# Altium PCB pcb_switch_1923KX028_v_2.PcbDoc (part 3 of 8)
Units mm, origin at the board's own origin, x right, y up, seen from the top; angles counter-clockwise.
Board outline 297.2 x 112.05 mm, 6 copper layers (Component Side, GND Layer 1, Inner Layer 1, Inner Layer 2, GND Layer 2, Solder Side), stack 1.578 mm thick; 545 components, 377 nets, 3174 pads, 1537 vias.
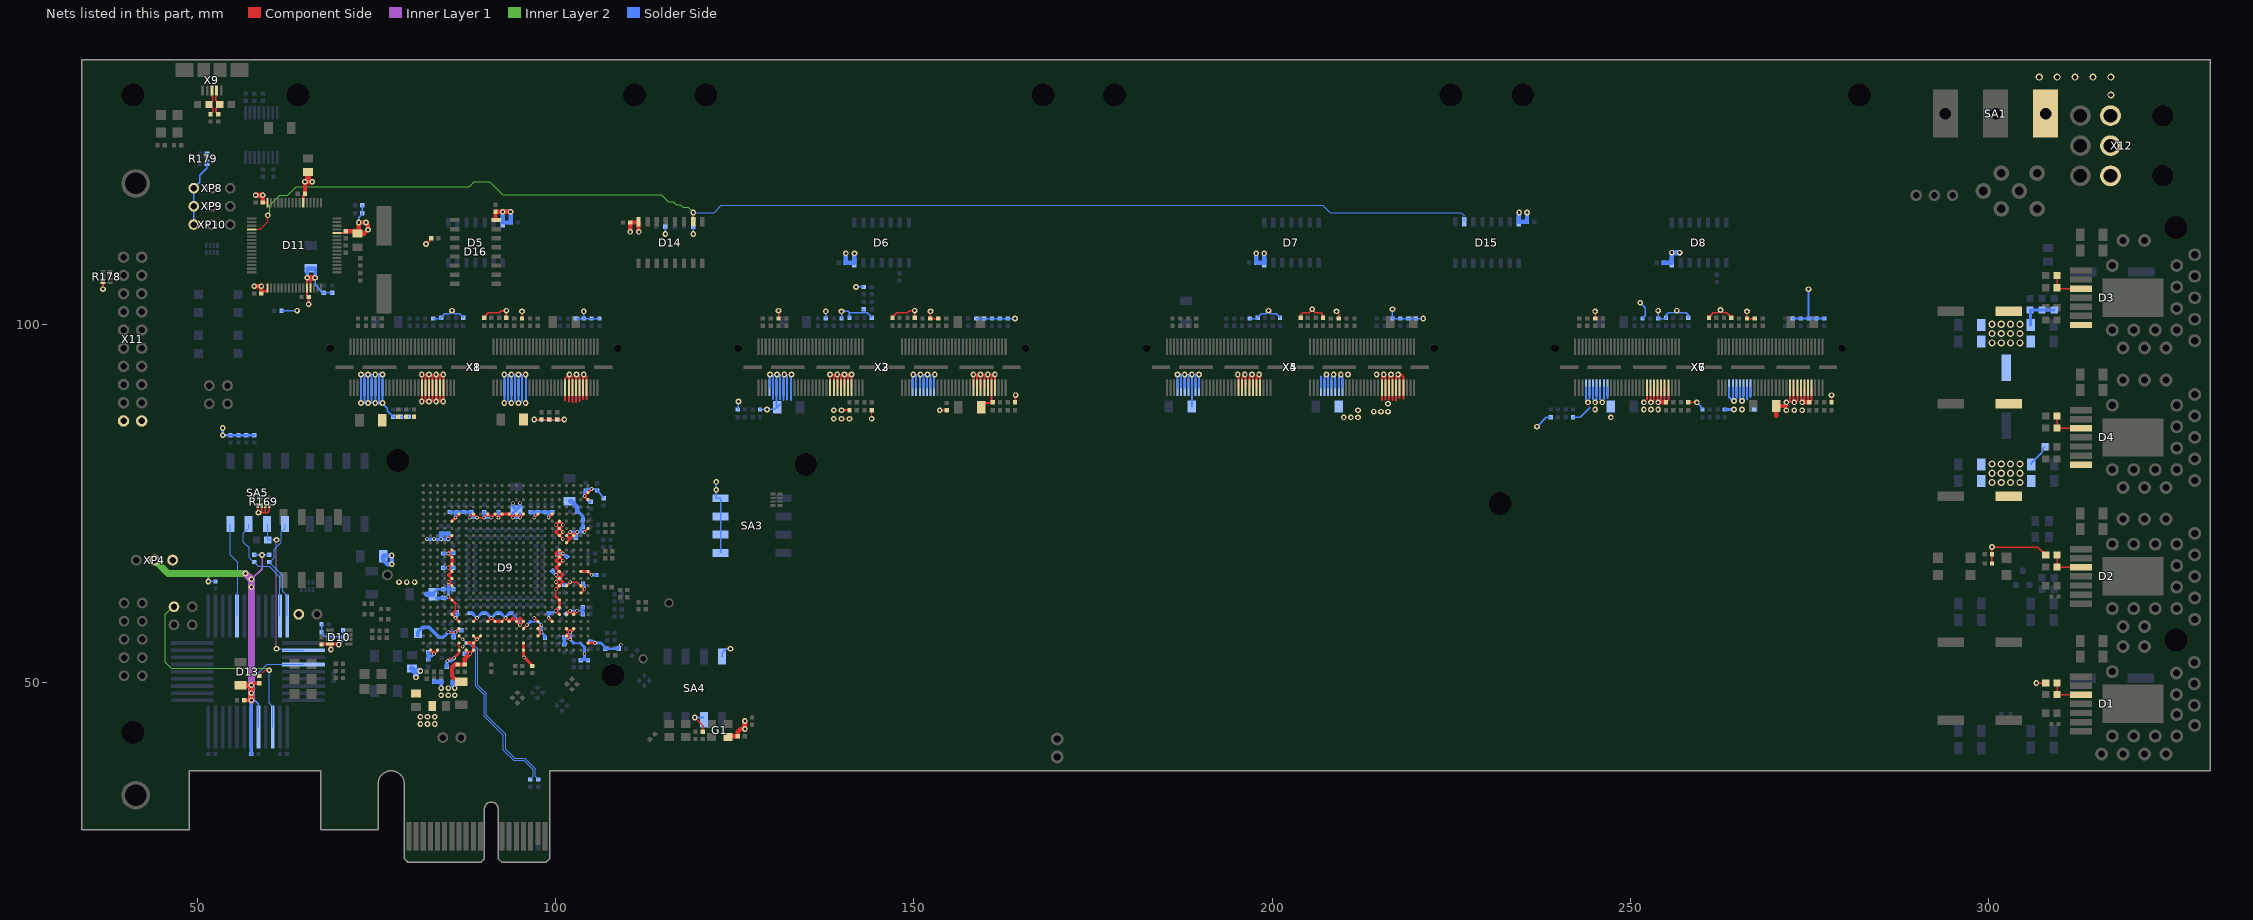
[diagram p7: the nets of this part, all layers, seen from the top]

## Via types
v1: diameter 0.8, hole 0.4, Component Side to Solder Side, tented both sides, 884 vias
v2: diameter 0.5, hole 0.3, Component Side to Solder Side, tented both sides, 269 vias
v3: diameter 1, hole 0.6, Component Side to Solder Side, tented both sides, 95 vias
v4: diameter 0.5/0.5/0.3/0.3/0.5/0.5 (per signal layer), hole 0.3, Component Side to Solder Side, tented both sides, 80 vias
v5: diameter 0.5/0.3/0.3/0.5/0.3/0.5 (per signal layer), hole 0.3, Component Side to Solder Side, tented both sides, 37 vias
v6: diameter 0.5/0.3/0.3/0.3/0.3/0.5 (per signal layer), hole 0.3, Component Side to Solder Side, tented both sides, 34 vias
v7: diameter 0.5/0.5/0.5/0.3/0.5/0.5 (per signal layer), hole 0.3, Component Side to Solder Side, tented both sides, 29 vias
v8: diameter 0.5, hole 0.3, Component Side to Solder Side, 25 vias
v9: diameter 0.5/0.3/0.5/0.3/0.3/0.5 (per signal layer), hole 0.3, Component Side to Solder Side, tented both sides, 25 vias
v10: diameter 0.5/0.5/0.3/0.5/0.5/0.5 (per signal layer), hole 0.3, Component Side to Solder Side, tented both sides, 19 vias
v11: diameter 0.6, hole 0.3, Component Side to Solder Side, tented both sides, 14 vias
v12: diameter 0.8, hole 0.5, Component Side to Solder Side, tented both sides, 11 vias
v13: diameter 0.5/0.3/0.5/0.5/0.3/0.5 (per signal layer), hole 0.3, Component Side to Solder Side, tented both sides, 7 vias
v14: diameter 0.8, hole 0.4, Component Side to Solder Side, 5 vias
v15: diameter 0.5/0.5/0.5/0.5/0.5/0.5 (per signal layer), hole 0.3, Component Side to Solder Side, tented both sides, 2 vias
v16: diameter 0.8, hole 0.5, Component Side to Solder Side, 1 vias

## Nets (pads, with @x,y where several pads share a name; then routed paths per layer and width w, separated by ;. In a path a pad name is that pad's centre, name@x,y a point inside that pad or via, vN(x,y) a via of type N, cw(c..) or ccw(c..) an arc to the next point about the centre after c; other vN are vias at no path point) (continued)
+3.3V: C4.1 C5.1 C11.1 C12.1 C13.1 C15.1 C16.1 C17.1 C18.2 C19.1 C21.1 C23.1 C25.1 C27.1 C29.1 C31.2 C32.2 C33.2 C34.2 C35.1 C40.1 C56.1 C65.1 C66.1 C74.1 C75.1 C83.1 C85.1 C96.2 C108.1 C119.2 C121.2 C122.2 C123.2 C124.2 C125.1 C126.2 C139.1 C155.1 C159.1 C160.1 C161.1 C162.1 C163.1 C164.1 C165.1 C166.1 C167.1 C168.1 C169.1 C170.1 C172.1 C174.1 C175.1 C176.1 C177.1 C178.1 C179.1 C180.1 C181.1 C182.1 C183.1 C184.1 C187.1 C190.1 C223.1 C228.1 C229.1 C230.1 C231.1 C232.1 C233.1 C234.1 C235.1 C236.1 C237.1 C238.1 D3.7 D4.7 D5.14 D6.14 D7.14 D8.14 D9.AC24 D9.AD2 D9.AD3 D9.B24 D9.C24 D9.E6 D9.E8 D9.E10 D9.E11 D9.E12 D9.E13 D9.E14 D9.E15 D9.E17 D9.E19 D9.F5 D9.F20 D9.G20 D9.H5 D9.H20 D9.K5 D9.K20 D9.L5 D9.L20 D9.M5 D9.M20 D9.N5 D9.N20 D9.P5 D9.P20 D9.R5 D9.R20 D9.U5 D9.U20 D9.V20 D9.W5 D9.W20 D9.Y6 D9.Y8 D9.Y10 D9.Y11 D9.Y12 D9.Y13 D9.Y14 D9.Y15 D9.Y17 D9.Y19 D10.8 D11.1 D11.12 D11.13 D11.28 D11.38 D11.48 D14.16 D15.16 D16.16 G1.4 L1.1 L4.1 L5.1 L6.2 R4.2 R5.2 R6.1 R13.1 R14.1 R15.1 R16.1 R17.1 R18.1 R19.1 R20.1 R25.1 R26.1 R27.1 R28.1 R29.1 R31.2 R32.1 R33.1 R36.1 R43.1 R51.1 R53.2 R57.2 R59.1 R60.1 R61.1 R66.1 R67.1 R68.1 R69.1 R72.1 R73.1 R74.1 R75.1 R76.1 R77.1 R84.1 R85.1 R88.1 R89.1 R90.1 R91.1 R92.1 R93.1 R98.1 R99.1 R100.1 R101.1 R103.1 R104.1 R109.2 R110.2 R112.1 R113.1 R116.2 R117.2 R122.2 R124.2 R126.2 R131.2 R147.2 R150.2 R152.1 R154.2 R156.2 R158.2 R161.2 R164.2 R165.2 R167.2 R169.1 R169.2 R169.3 R169.4 R171.1 R173.1 R175.1 R176.2 R177.2 R178.4 R179.5 R179.6 R179.7 R179.8 R181.1 R182.1 R183.1 R184.1 R185.1 R186.2 R189.2 R196.2 R199.2 R204.2 R206.2 R208.2 R209.2 R210.2 R211.2 R212.2 R213.2 R217.2 R218.2 R219.2 R228.1 R229.1 R230.1 R231.1 R232.1 R233.1 R234.1 SA3.1 SA3.2 SA3.3 SA3.4 SA4.4 X1.41 X1.43 X1.45 X1.47 X1.49 X1.51 X1.53 X1.101 X1.103 X1.105 X1.107 X1.109 X1.111 X1.113 X2.41 X2.43 X2.45 X2.47 X2.49 X2.51 X2.53 X2.101 X2.103 X2.105 X2.107 X2.109 X2.111 X2.113 X3.41 X3.43 X3.45 X3.47 X3.49 X3.51 X3.53 X3.101 X3.103 X3.105 X3.107 X3.109 X3.111 X3.113 X4.41 X4.43 X4.45 X4.47 X4.49 X4.51 X4.53 X4.101 X4.103 X4.105 X4.107 X4.109 X4.111 X4.113 X5.41 X5.43 X5.45 X5.47 X5.49 X5.51 X5.53 X5.101 X5.103 X5.105 X5.107 X5.109 X5.111 X5.113 X6.41 X6.43 X6.45 X6.47 X6.49 X6.51 X6.53 X6.101 X6.103 X6.105 X6.107 X6.109 X6.111 X6.113 X7.41 X7.43 X7.45 X7.47 X7.49 X7.51 X7.53 X7.101 X7.103 X7.105 X7.107 X7.109 X7.111 X7.113 X8.41 X8.43 X8.45 X8.47 X8.49 X8.51 X8.53 X8.101 X8.103 X8.105 X8.107 X8.109 X8.111 X8.113 X11.1 X11.2 XP4.3 XP8.1 XP9.1 XP10.1 XP11.1 | length 672.1
  Component Side w0.15: v1(144.1,86.8) R18.1@144.1,88
  Component Side w0.2: R169.1@58.4,74.725 58.4,73.7 v1(58.5,73.7) 58.95,73.7 ; R169.2@58.95,74.725 58.95,73.7 ; R169.3@59.45,74.725 59.45,73.7 ; R169.4@60,74.725 60,74 59.7,73.7 59.45,73.7 ; v1(81.9,111.2) 82.6,111.9 R234.1@82.6,112 ; 86,60 86,61 ; v6(89,73) v6(90,73) ; R27.1@90,100.9 90,101 90.6,101.6 92.1,101.6 92.4,101.9 v1(93.1,101.9) R28.1@93.1,100.9 ; R147.2@95.3,100.8 v1(95.3,101.8) ; v1(97,86.7) R184.1@98,86.7 R185.1@99.1,86.7 R183.1@100.2,86.7 v1(101.2,86.7) ; 100,62 v9(100,63) ; R131.2@131.1,100.8 v1(131.1,101.9) ; R29.1@147,100.9 147,101 147.6,101.6 149.1,101.6 149.4,101.9 v1(150.1,101.9) R32.1@150.1,100.9 ; v1(152.3,101.8) R156.2@152.3,100.8 R158.2@153.4,100.8 ; v1(153.6,88) R100.1@154.6,88 ; R72.1@204,100.9 204,101.3 204.3,101.6 205.2,101.6 205.6,102 206,101.6 206.8,101.6 207.1,101.3 R73.1@207.1,100.9 ; v1(209,101.8) 209.3,101.5 R204.2@209.3,100.8 ; R196.2@245.1,100.8 v1(245.1,101.8) ; R69.1@258.1,89.1 v1(259.3,89.1) ; R76.1@261,100.9 261,101 261.6,101.6 262.2,101.6 v1(262.6,102) 263,101.6 263.5,101.6 264.1,101 R77.1@264.1,100.9 ; v1(266.3,101.8) R206.2@266.3,100.8 R208.2@267.4,100.8 ; R85.1@278.1,89.1 v1(278.1,90.1) ; R31.2@300.5,66.6 R33.1@300.5,67.9 v1(300.5,68.9) 306.9,68.9 R43.1@308,67.8 ; v1(306.7,49.9) R36.1@308,49.9 ; 58.95,73.7 59.45,73.7
  Component Side w0.28: v1@81.315,89.215 X1.41@81.315,91.135 v1@81.315,92.985 ; 81.815,89.215 X1.43@81.815,91.135 81.815,92.985 ; v1@82.315,89.215 X1.45@82.315,91.135 v1@82.315,92.985 ; 82.815,89.215 X1.47@82.815,91.135 82.815,92.985 ; v1@83.315,89.215 X1.49@83.315,91.135 v1@83.315,92.985 ; 83.815,89.215 X1.51@83.815,91.135 83.815,92.985 ; v1@84.315,89.215 X1.53@84.315,91.135 v1@84.315,92.985 ; 101.32,89.38 X1.101@101.32,91.135 101.32,92.42 101.6,92.7 ; 101.82,89.22 X1.103@101.82,91.135 v1@101.82,92.78 ; 102.32,89.12 X1.105@102.32,91.135 102.32,92.72 ; 102.82,89.18 X1.107@102.82,91.135 v1@102.82,92.78 ; 103.32,89.28 X1.109@103.32,91.135 103.32,92.72 ; 103.82,89.58 X1.111@103.82,91.135 v1@103.82,92.78 ; 104.32,89.52 X1.113@104.32,91.135 104.32,92.72 ; X2.41@138.315,91.135 v1@138.315,92.985 ; X2.43@138.815,91.135 138.815,92.985 ; X2.45@139.315,91.135 v1@139.315,92.985 ; X2.47@139.815,91.135 139.815,92.985 ; v1(139.9,88) R17.1@141,88 ; X2.49@140.315,91.135 v1@140.315,92.985 ; X2.51@140.815,91.135 140.815,93.085 ; X2.53@141.315,91.135 v1@141.315,92.985 ; X2.101@158.32,91.135 v1@158.32,92.98 ; X2.103@158.82,91.135 158.82,93.08 ; X2.105@159.32,91.135 v1@159.32,92.98 ; C21.1@159.4,88.4 160,89 160.92,89 R51.1@161.02,89.1 ; X2.107@159.82,91.135 159.82,92.98 ; X2.109@160.32,91.135 v1@160.32,92.98 ; R51.1@160.82,89.1 X2.111@160.82,91.135 160.82,93.08 ; X2.113@161.32,91.135 v1@161.32,92.98 ; R59.1@164.12,89.1 164.2,89.18 v1(164.2,90.1) ; X4.41@195.315,91.135 v1@195.315,92.885 ; X4.43@195.815,91.135 195.815,92.615 ; X4.45@196.315,91.135 v1@196.315,92.885 ; X4.47@196.815,91.135 196.815,92.615 ; X4.49@197.315,91.135 v1@197.315,92.885 ; X4.51@197.815,91.135 197.815,92.785 ; X4.53@198.315,91.135 v1@198.315,92.885 ; 215.32,89.42 X4.101@215.32,91.135 v1@215.32,92.72 ; 215.82,89.48 X4.103@215.82,91.135 v1@215.82,92.78 ; 216.32,89.42 X4.105@216.32,91.135 v1@216.32,92.72 ; 216.82,89.42 X4.107@216.82,91.135 v1@216.82,92.78 ; 217.32,89.38 X4.109@217.32,91.135 v1@217.32,92.72 ; v1(217.6,93) 218,93 218.32,92.68 X4.113@218.32,91.135 218.32,89.62 ; 217.82,89.72 X4.111@217.82,91.135 v1@217.82,92.78 ; 252.315,89.515 X6.41@252.315,91.135 ; 252.815,89.515 X6.43@252.815,91.135 ; 253.315,89.415 X6.45@253.315,91.135 ; v1@253.815,89.185 X6.47@253.815,91.135 ; v1(253.9,89.1) 254.315,89.515 X6.49@254.315,91.135 ; X6.51@254.815,91.135 254.815,89.285 R68.1@255,89.1 255.315,89.415 X6.53@255.315,91.135 ; 272.32,89.12 X6.101@272.32,91.135 ; v1@272.82,89.18 X6.103@272.82,91.135 ; 273.32,89.28 X6.105@273.32,91.135 ; v1@273.82,89.28 X6.107@273.82,91.135 ; 274.32,89.42 X6.109@274.32,91.135 ; R84.1@274.82,89.28 X6.111@274.82,91.135 ; R84.1@275,89.1 275.32,89.42 X6.113@275.32,91.135
  Component Side w0.3: v1(36.8,104.9) R178.4@36.8,105.8 ; C122.2@58.9,104.3 58.9,104.6 59.75,104.6 D11.1@59.75,105.05 ; C124.2@59.1,117 59.7,117 D11.48@59.75,116.95 ; D11.38@64.75,116.95 64.75,117.95 C126.2@65,118.2 ; v1@65.25,106.5 D11.12@65.25,105.05 65.25,104.05 C123.2@65.5,103.8 v1(65.5,102.8) ; D11.13@65.75,105.05 65.75,106.5 ; D11.28@69.45,112.75 70.45,112.75 C119.2@70.7,113
  Component Side w0.4: C96.2@67.3,55.3 67.3,55.35 D10.8@68.5,55.35 D10.8@68.6,55.35 ; v1(68.6,54.6) D10.8@68.6,55.35 ; v1(69.7,55.3) 69.65,55.35 D10.8@68.6,55.35 ; D9.AD2@82.5,54.5 v7(83,54) D9.AD3@83.5,54.5 ; v7(85,62) D9.U5@85.5,61.5 86,61 ; v7(85,70) D9.H5@85.5,70.5 ; D9.R5@85.5,63.5 v7(85,64) D9.P5@85.5,64.5 85,65 D9.N5@85.5,65.5 v7(85,66) D9.M5@85.5,66.5 D9.L5@85.5,67.5 v7(85,68) D9.K5@85.5,68.5 ; D9.F5@85.5,72.5 D9.E6@86.5,73.5 ; 86,60 D9.W5@85.5,59.5 D9.Y6@86.5,58.5 ; v6(88,73) D9.E8@88.5,73.5 v6(89,73) ; D9.Y8@88.5,58.5 v9(89,59) ; v6(90,73) D9.E10@90.5,73.5 v6(91,73) D9.E11@91.5,73.5 v6(92,73) D9.E12@92.5,73.5 D9.E13@93.5,73.5 v6(94,73) D9.E14@94.5,73.5 v6(95,73) D9.E15@95.5,73.5 ; D9.Y10@90.5,58.5 v9(91,59) D9.Y11@91.5,58.5 D9.Y12@92.5,58.5 v9(93,59) D9.Y13@93.5,58.5 94,59 D9.Y14@94.5,58.5 v9(95,58) 95.5,58.5 95,59 D9.Y14@94.5,58.5 ; v9(97,59) D9.Y17@97.5,58.5 ; v9(97,73) D9.E17@97.5,73.5 ; v9(99,59) D9.Y19@99.5,58.5 ; v9(99,73) D9.E19@99.5,73.5 ; 100,62 D9.U20@100.5,61.5 D9.V20@100.5,60.5 v9(100,60) D9.W20@100.5,59.5 ; v9(100,63) D9.R20@100.5,63.5 ; v9(101,68) D9.L20@100.5,67.5 ; v9(101,68) D9.K20@100.5,68.5 100,68 D9.L20@100.5,67.5 ; v9(101,70) D9.H20@100.5,70.5 ; D9.C24@104.5,75.5 v2(104,76) v2(105,77) ; D9.AC24@104.5,55.5 v2(105.5,55.5) ; D9.R20@100.5,63.5 101,64 D9.P20@100.5,64.5 ; D9.R20@100.5,63.5 v9(100,64) D9.P20@100.5,64.5 ; D9.P20@100.5,64.5 101,65 D9.N20@100.5,65.5 ; D9.P20@100.5,64.5 v9(100,65) D9.N20@100.5,65.5 ; D9.N20@100.5,65.5 100,66 D9.M20@100.5,66.5 ; D9.M20@100.5,66.5 100,67 D9.L20@100.5,67.5 ; D9.M20@100.5,66.5 v9(101,67) D9.L20@100.5,67.5 ; D9.H20@100.5,70.5 v9(101,71) D9.G20@100.5,71.5 ; D9.H20@100.5,70.5 100,71 D9.G20@100.5,71.5 ; D9.G20@100.5,71.5 v9(101,72) D9.F20@100.5,72.5 100,72 D9.G20@100.5,71.5
  Component Side w0.6: v1(57.9,105.3) v1(58.9,105.3) 58.9,104.6 ; C124.2@59.1,117 v1(59.1,118) ; C126.2@65,118.2 v1(65,119.9) ; C119.2@70.7,113 L4.1@72.5,113 ; D16.16@91.7,114.545 91.6,114.645 C18.2@91.6,115.7 v1(92.6,115.7) v1(93.7,115.7) ; v1(110.4,112.9) C11.1@110.4,114.2 111.555,114.2 111.555,112.9 v1(111.6,112.9) ; G1.4@124.025,42.5 C223.1@125.4,42.5 125.4,43.1 125.8,43.5 v1(126.4,43.5) ; v1(253.9,89.1) R68.1@255,89.1 ; 270.4,87.2 C29.1@270.4,88.6 271.7,88.6 ; v1(274,89.1) R84.1@275,89.1 ; L4.1@72.5,113 72.5,112.85 L4.1@72.3,112.65 73.25,112.65 v1(73.8,113.2) 73.8,113.9 v1(73.5,114.2) v1(72.5,114.2) L4.1@72.5,113
  Component Side w0.8: v1(58.1,118) v1(59.1,118) ; v1(65,119.9) v1@65.4,119.9 ; v1(65.3,106.5) 65.75,106.5 v1(66.4,106.5) ; L6.2@65.4,121.25 v1@65.4,119.9 ; v1(66,119.9) v1@65.4,119.9 ; v1(126.4,43.5) v1(126.4,44.6)
  Solder Side w0.2: XP8.1@48.96,119 XP8.1@49,119.04 ; XP10.1@49.46,113.92 XP9.1@49.46,116.46 XP8.1@49.46,119 49.5,119 50.3,119.8 50.3,120.8 51.3,121.8 R179.5@51.3,122.3 R179.8@51.3,123.9 ; R175.1@61.7,101.9 v1(63.9,101.9) ; v1(66.4,106.5) 66.4,105.5 67.5,104.4 R171.1@67.6,104.4 R173.1@68.8,104.4 ; R177.2@67.3,58.1 R176.2@67.3,57 67.3,56.9 67.8,56.4 70.2,56.4 R109.2@70.3,56.3 ; v1(69.7,55.3) 70.3,55.9 R109.2@70.3,56.3 ; R110.2@70.3,57.3 R109.2@70.3,56.3 ; v1(72.5,114.2) 72.5,114.9 73,115.4 R6.1@73,115.5 R152.1@73,116.6 ; v1@75.8,89.2 v1(75.8,89) 76.5,88.3 76.5,87.9 R231.1@77.3,87.1 R232.1@78.4,87.1 R233.1@79.5,87.1 ; R218.2@82.9,100.8 83.9,100.8 R103.1@84,100.9 84,101 84.5,101.5 85.1,101.5 v1(85.5,101.9) 85.9,101.5 86.6,101.5 87.1,101 R101.1@87.1,100.9 ; C178.1@93.8,59.7 C160.1@94.8,58.7 ; v1(97,86.7) R228.1@98,86.7 R229.1@99.1,86.7 R230.1@100.2,86.7 v1(101.2,86.7) ; R212.2@102.8,100.8 R210.2@103.9,100.8 ; v1(103.9,101.8) R210.2@103.9,100.8 ; C231.1@105.8,76.8 105.8,76.6 105.9,76.6 106.7,75.8 R181.1@106.7,75.7 ; R90.1@106.1,100.8 R91.1@105,100.8 R210.2@103.9,100.8 ; v1(115.3,112.6) R116.2@115.3,113.6 ; v1(119.2,112.6) R117.2@119.2,113.6 ; v1(122.4,78) 122.4,75.71 SA3.4@123,75.71 SA3.3@123,73.17 SA3.2@123,70.63 SA3.1@123,68.09 ; SA4.4@123.21,53.6 123.21,54.11 123.8,54.7 v1(124.4,54.7) ; R60.1@125.4,88.1 125.5,88.2 v1(125.5,89.2) ; R61.1@128.5,88.1 v1(129.5,88.1) 130.6,88.1 C23.1@130.9,88.4 ; R154.2@137.7,100.8 v1(137.7,101.8) ; R150.2@139.9,100.8 v1(139.9,101.8) 140.8,101.8 141,101.6 ; R26.1@141,100.9 141,101.6 ; v1(141.9,105.2) R19.1@143,105.2 ; 143,101.6 R20.1@143,102.1 ; R25.1@144.1,100.9 144.1,101 143.5,101.6 141,101.6 ; R126.2@158.7,100.8 R124.2@159.8,100.8 R122.2@160.9,100.8 R16.1@162,100.8 R14.1@163.1,100.8 v1(164.1,100.8) ; R199.2@196.9,100.8 197.9,100.8 R75.1@198,100.9 198,101 198.5,101.5 199.1,101.5 v1(199.5,101.9) 199.9,101.5 200.6,101.5 201.1,101 R74.1@201.1,100.9 ; v1(216.8,102.1) R189.2@216.8,100.8 R186.2@217.9,100.8 R67.1@219,100.8 R66.1@220.1,100.8 v1(221.1,100.8) ; v1(237,85.7) 238.3,87 R112.1@238.9,87 ; R113.1@242,87 243,87 244.4,88.4 ; v1(251.4,103) 252.1,102.3 252.1,101.2 R219.2@251.7,100.8 ; v1(253.9,101.9) R217.2@253.9,100.8 254.9,100.8 R99.1@255,100.9 255,101.3 255.3,101.6 256.2,101.6 v1(256.5,101.9) 256.8,101.6 257.8,101.6 258.1,101.3 R98.1@258.1,100.9 ; v1(259.3,89.1) 259.9,88.5 259.9,88.3 R92.1@260.1,88.1 ; C74.1@306,80.4 306,80.6 307.5,82.1 307.5,82.5 R57.2@307.9,82.9
  Solder Side w0.28: v1@72.81,89 X8.113@72.81,91.135 v1@72.81,93 ; 73.31,89 X8.111@73.31,91.135 73.31,93 ; v1@73.81,89 X8.109@73.81,91.135 v1@73.81,93 ; 74.31,89.1 X8.107@74.31,91.135 74.31,93 ; v1@74.81,89 X8.105@74.81,91.135 v1@74.81,93 ; 75.31,88.9 X8.103@75.31,91.135 75.31,93.1 ; v1@75.81,89 X8.101@75.81,91.135 v1@75.81,93 ; v1@92.815,89.2 X8.53@92.815,91.135 v1@92.815,93 ; 93.315,89.3 X8.51@93.315,91.135 93.315,93 ; v1@93.815,89.2 X8.49@93.815,91.135 v1@93.815,93 ; 94.315,89.3 X8.47@94.315,91.135 94.315,93 ; v1@94.815,89.2 X8.45@94.815,91.135 v1@94.815,93 ; 95.315,89.2 X8.43@95.315,91.135 95.315,93 ; v1@95.815,89.2 X8.41@95.815,91.135 v1@95.815,93 ; X3.113@129.81,91.135 v1@129.81,92.91 ; 130.31,89.59 X3.111@130.31,91.135 130.31,92.89 ; v1@130.81,92.91 X3.109@130.81,91.135 130.81,88.49 C23.1@130.9,88.4 C23.1@131.31,88.81 ; 131.31,89.51 X3.107@131.31,91.135 131.31,92.89 ; 131.81,89.41 X3.105@131.81,91.135 v1@131.81,92.91 ; 132.31,89.49 X3.103@132.31,91.135 132.31,92.89 ; 132.81,89.41 X3.101@132.81,91.135 v1@132.81,92.91 ; X3.53@149.815,91.135 v1@149.815,92.915 ; X3.51@150.315,91.135 150.315,92.885 ; X3.49@150.815,91.135 v1@150.815,92.915 ; X3.47@151.315,91.135 151.315,92.885 v1@151.785,92.885 ; X3.45@151.815,91.135 v1@151.815,92.855 ; X3.43@152.315,91.135 152.315,92.885 ; X3.41@152.815,91.135 v1@152.815,92.915 ; X5.113@186.81,91.135 v1@186.81,92.99 ; X5.111@187.31,91.135 187.31,92.99 ; X5.109@187.81,91.135 v1@187.81,92.99 ; X5.107@188.31,91.135 188.31,93.01 ; C27.1@188.8,88.5 188.81,88.51 X5.105@188.81,91.135 v1@188.81,92.99 ; X5.103@189.31,91.135 189.31,92.99 ; X5.101@189.81,91.135 v1@189.81,92.99 ; X5.53@206.815,91.135 206.815,92.715 ; X5.51@207.315,91.135 207.315,92.715 ; X5.49@207.815,91.135 v1@207.815,92.785 ; X5.47@208.315,91.135 208.315,92.715 ; X5.45@208.815,91.135 v1@208.815,92.785 ; X5.43@209.315,91.135 209.315,92.715 ; X5.41@209.815,91.135 v1@209.815,92.785 ; 243.81,89.39 X7.113@243.81,91.135 ; 244.31,89.61 X7.111@244.31,91.135 ; 244.81,89.51 X7.109@244.81,91.135 ; 245.31,89.51 X7.107@245.31,91.135 ; 245.81,89.51 X7.105@245.81,91.135 ; 246.31,89.59 X7.103@246.31,91.135 ; 246.81,89.71 X7.101@246.81,91.135 ; X7.53@263.815,91.135 263.815,89.785 264.1,89.5 ; v1@264.315,89.485 X7.51@264.315,91.135 ; 264.815,89.615 X7.49@264.815,91.135 ; v1@265.315,89.515 X7.47@265.315,91.135 ; v1@265.815,89.515 X7.45@265.815,91.135 ; 266.315,89.515 X7.43@266.315,91.135 ; 266.815,89.815 X7.41@266.815,91.135 ; R213.2@272.7,100.8 R211.2@273.8,100.8 R209.2@274.9,100.8 ; v1(274.9,104.9) R209.2@274.9,100.8 ; R88.1@277.1,100.8 R89.1@276,100.8 R209.2@274.9,100.8
  Solder Side w0.3: v1(53.5,85.5) v1(53.5,84.5) R165.2@57.9,84.5 ; v2(105,77) 105.6,77 C231.1@105.8,76.8
  Solder Side w0.4: 82.2,53.7 82.7,53.7 v7(83,54) ; C4.1@82.8,62.3 83.5,63 C229.1@84.3,63 85,63 ; C4.1@83.3,61.8 C176.1@84.3,61.8 84.8,61.8 v7(85,62) 85,63 ; C235.1@84.3,66 v7(85,66) C168.1@85.7,66 ; C164.1@84.3,68 v7(85,68) 85.6,68 C175.1@85.7,68.1 ; v7(85,64) 85,63 ; C228.1@85.2,73.8 C174.1@86.2,73.8 C170.1@87.2,73.8 C183.1@88.2,73.8 ; C187.1@85.7,63 85,63 ; v7(86,59) 86.2,59.2 C159.1@86.2,59.8 ; v6(86,73) C174.1@86,73.6 ; C177.1@88,59.8 88.2,59.8 v9(89,59) 89.8,59.8 90,59.8 90.2,59.8 v9(91,59) 91.8,59.8 92,59.8 92.2,59.8 v9(93,59) 93,59.151 93.649,59.8 C178.1@93.8,59.8 ; C183.1@88,73.6 v6(88,73) v6(89,73) ; C163.1@90,73.8 v6(90,73) v6(91,73) ; v6(92,73) C169.1@92,73.8 ; C5.1@94.5,74.1 94,73.6 v6(94,73) v6(95,73) C5.1@95,73.6 ; C160.1@94.8,58.8 94.8,58.2 v9(95,58) ; C139.1@96.5,73.8 97,73.8 ; v9(97,73) 97,73.8 ; v9(99,59) 99,59.8 99.8,59.8 v9(100,60) C233.1@100.446,60.446 ; v9(99,73) 99,73.8 ; C182.1@99.5,73.8 C179.1@98.5,73.8 C230.1@97.5,73.8 97,73.8 ; C232.1@99.546,65.546 99.546,65.454 v9(100,65) 100.454,64.546 C166.1@100.546,64.546 v9(100,64) ; C184.1@100.2,67.9 100.3,68 v9(101,68) 101.454,67.546 C162.1@101.546,67.546 ; C108.1@104.8,55.7 105.3,55.7 v2(105.5,55.5) 106,55.5 106.3,55.5 106.8,55 106.8,54.7 C125.1@108.7,54.7 ; C180.1@104.8,75.2 v2(104,76) 104,76.6 104.4,77 v2(105,77) ; C125.1@108.7,54.6 108.7,54.85 v2(109.1,55.25) ; R93.1@263.2,88.1 v1(264.5,88.1) ; C65.1@305.9,99.9 305.9,101.9 R5.2@305.8,102 R4.2@307.5,102 R53.2@309.2,102
  Solder Side w0.5: v1(65.3,106.5) C121.2@65.3,107.7 ; C121.2@66.3,107.7 C121.2@65.3,107.7 ; v1(66.4,106.5) 66.4,107.8 C121.2@65.8,107.8 65.3,107.8 C121.2@65.3,107.7 ; v7(82,70) v7(83,70) v7(84,70) v7(85,70) ; C238.1@82.2,53.2 82.2,53.7 C237.1@82.2,54.2 ; v2(94,75) 94,74.6 C5.1@94.5,74.1 95,74.6 v2(95,75)
  Solder Side w0.6: v7(84,70) C161.1@84,70.8 C236.1@85,70.8 v7(85,70) ; v1(140.5,109.9) C32.2@140.5,108.6 D6.14@141.69,108.6 141.69,109.89 v1(141.7,109.9) ; v1(197.8,109.9) C33.2@197.8,108.6 D7.14@198.89,108.6 198.89,109.89 v1(198.9,109.9) ; v1(234.5,115.6) 234.445,115.545 D15.16@234.445,114.3 C15.1@235.6,114.3 v1(235.6,115.6) ; C34.2@254.7,108.6 D8.14@255.79,108.6 v1@255.79,109.99 ; C172.1@75.9,67.1 76.5,66.5 v1(77.1,66.5) v1(77.1,67.7) 76,67.7 C172.1@75.9,67.6 C172.1@75.9,67.1 ; v1(92.6,115.7) v1(93.7,115.7) C31.2@93.7,114.2 D5.14@92.61,114.2 92.61,115.69 v1(92.6,115.7)
  Solder Side w0.8: v1(65.3,106.5) v1(66.4,106.5) ; L1.1@79.9,51.95 L1.1@80.25,51.6 ; v1(80.5,50.7) 80.5,51.35 L1.1@80.25,51.6 ; v1(81.1,51.6) L1.1@80.25,51.6 ; 82,62.3 C4.1@82.8,62.3 ; v1(255.8,110) v1(256.9,110)
  other v1: 81.1,44.2 82.1,44.2 83.1,44.2 81.1,45.2 82.1,45.2 83.1,45.2 78.1,64 79.2,64 80.3,64 122.4,76.9 138.8,86.8 139.9,86.8 141,86.8 210,87 211,87 212,87 247.3,87 214.2,87.8 215.2,87.8 216.2,87.8 138.8,88 212,88 271.8,88 272.9,88 274,88 245.1,88.1 251.9,88.1 252.9,88.1 253.9,88.1 265.6,88.1 216.2,88.9 72.8,89 73.8,89 74.8,89 92.8,89 93.8,89 94.8,89 95.8,89 244.1,89.1 245.1,89.1 246.1,89.1 251.9,89.1 252.9,89.1 271.8,89.1 272.9,89.1 81.3,89.2 82.3,89.2 83.3,89.2 84.3,89.2 264.5,89.3 265.6,89.3 72.8,93 73.8,93 74.8,93 75.8,93 81.3,93 82.3,93 83.3,93 84.3,93 92.8,93 93.8,93 94.8,93 95.8,93 101.9,93 102.9,93 103.9,93 129.9,93 130.9,93 131.9,93 132.9,93 138.3,93 139.3,93 140.3,93 141.3,93 149.9,93 150.9,93 151.9,93 152.9,93 158.3,93 159.3,93 160.3,93 161.3,93 186.8,93 187.8,93 188.8,93 189.8,93 195.2,93 196.2,93 197.2,93 198.2,93 207.6,93 208.6,93 209.6,93 210.6,93 214.6,93 215.6,93 216.6,93 205.6,102.1
  other v3: 300.5,77.9 301.8,77.9 303.1,77.9 304.4,77.9 300.5,79.2 301.8,79.2 303.1,79.2 304.4,79.2 300.5,80.5 301.8,80.5 303.1,80.5 304.4,80.5 300.5,97.4 301.8,97.4 303.1,97.4 304.4,97.4 300.5,98.7 301.8,98.7 303.1,98.7 304.4,98.7 300.5,100 301.8,100 303.1,100 304.4,100
  other v9: 100,72
+12: SA1.1 X12.1 X12.2 X12.3
  other v3: 317.1,132 307.1,134.5 309.6,134.5 312.1,134.5 314.6,134.5 317.1,134.5
_USB_D_N: C50.1 R7.2 X9.2 | length 4
  Component Side w0.22: X9.2@52.65,132.65 52.65,131.84 52.54,131.73 52.54,131.26 C50.1@53.1,130.7 52.565,130.165 52.565,129.635 R7.2@52.9,129.3
_USB_D_P: C51.1 R8.2 X9.3 | length 4
  Component Side w0.22: R8.2@51.8,129.3 52.135,129.635 52.135,130.165 C51.1@51.6,130.7 52.11,131.21 52.11,131.73 52,131.84 X9.3@52,132.65
CAP_PCI_E_TX_N: C100.2 D9.AB6 | length 25.9
  Component Side w0.15: D9.AB6@86.5,56.5 v4(87,56)
  Solder Side w0.15: v4(87,56) 87.345,55.655 88.128,55.655 89.11,54.673 89.11,49.6 90.31,48.4 90.31,45.428 93.01,42.728 93.01,40.69 94.29,39.41 95.673,39.41 97.155,37.928 97.155,36.87 C100.2@97.575,36.45
CAP_PCI_E_TX_P: C99.2 D9.AC6 | length 25.9
  Component Side w0.15: D9.AC6@86.5,55.5 86.35,55.411 ccw(c86.52,55.241) 86.52,55.001 ; 86.52,55 v4(87,55)
  Solder Side w0.15: v4(87,55) 87.345,55.345 88,55.345 88.8,54.545 88.8,49.472 90,48.272 90,45.3 92.7,42.6 92.7,40.562 94.162,39.1 95.545,39.1 96.845,37.8 96.845,36.87 C99.2@96.425,36.45
CLR#: D11.52 D14.10 D15.10 R117.1 | length 179.2
  Component Side w0.15: D11.52@57.55,113.25 58.75,113.25 59.8,114.3 v1(59.8,115.2) ; D14.10@119.175,114.3 119.2,114.325 v1(119.2,115.6)
  Inner Layer 2 w0.15: v1(59.8,115.2) 60.1,115.5 60.1,116.6 61.5,118 62.6,118 63.8,119.2 87.9,119.2 88.6,119.9 90.797,119.9 92.597,118.1 114.7,118.1 115.7,117.1 116.4,117.1 116.8,116.7 117.4,116.7 117.8,116.3 118.5,116.3 v1(119.2,115.6)
  Solder Side w0.15: R117.1@119.2,114.6 v1(119.2,115.6) 122.1,115.6 123.1,116.6 207.1,116.6 208.1,115.6 226.4,115.6 226.825,115.175 D15.10@226.825,114.3
D1_ENABLE: D1.3 R36.2 R40.1 | length 4.9
  Component Side w0.25: R36.2@309.63,49.87 309.63,48.27 D1.3@312.92,48.27 D1.3@312.89,48.3
D2_ENABLE: D2.3 R43.2 R46.1 | length 5
  Component Side w0.2: R46.1@309.6,66 309.67,66.07 D2.3@312.92,66.07 ; R46.1@309.6,66.1 R43.2@309.6,67.8
D3_ENABLE: D3.3 R49.2 R52.1 | length 5.1
  Component Side w0.2: R49.2@309.6,106.8 R52.1@309.6,105.1 309.73,104.97 D3.3@312.92,104.97 D3.3@312.89,105
D4_ENABLE: D4.3 R55.2 R56.1 | length 5.1
  Component Side w0.2: R56.1@309.6,85.3 309.77,85.47 D4.3@312.92,85.47 ; R56.1@309.6,85.5 R55.2@309.6,87.2
D9_1.1V: C149.1 C156.1 C157.1 C158.1 C171.1 C173.1 C196.1 C197.1 C198.1 C199.1 C200.1 C201.1 C204.1 C205.1 C206.1 C207.1 C208.1 C209.1 C210.1 C213.1 C214.1 C215.1 C216.1 C222.1 D9.AA15 D9.AA17 D9.AA21 D9.AA22 D9.AB8 D9.AB9 D9.AB17 D9.AB21 D9.AC7 D9.AC8 D9.AC15 D9.AD7 D9.AD8 D9.AD15 D9.G24 D9.H21 D9.H22 D9.J21 D9.N23 D9.N24 D9.R21 D9.R23 D9.T23 D9.W21 D9.W22 L3.1 | length 64.2
  Component Side w0.2: v9(102,64) 103,64 D9.R23@103.5,63.5
  Component Side w0.4: D9.AD7@87.5,54.5 v7(88,54) D9.AD8@88.5,54.5 D9.AC8@88.5,55.5 ; D9.AC7@87.5,55.5 D9.AC8@88.5,55.5 ; D9.AB8@88.5,56.5 v7(89,56) ; D9.AB9@89.5,56.5 v7(89,56) ; D9.AC15@95.5,55.5 95.5,53.6 v2(95.6,53.5) 96.7,52.4 C156.1@96.7,52.3 ; D9.AA15@95.5,57.5 v9(96,58) ; D9.AB17@97.5,56.5 v9(98,57) D9.AA17@97.5,57.5 v9(98,58) ; D9.W21@101.5,59.5 v9(102,60) D9.W22@102.5,59.5 v9(103,60) ; D9.R21@101.5,63.5 v9(102,64) ; D9.J21@101.5,69.5 102,70 ; D9.H22@102.5,70.5 v9(102,71) D9.H21@101.5,70.5 102,70 ; v13(103,71) 102,70 ; D9.T23@103.5,62.5 v2(104,63) D9.R23@103.5,63.5 ; D9.N23@103.5,65.5 D9.N24@104.5,65.5 v2(105,65) ; v2(104,71) D9.G24@104.5,71.5 ; D9.AC8@88.5,55.5 v7(89,56)
  Component Side w0.5: D9.AA21@101.5,57.5 v7(102,57) ; v7(102,56) D9.AB21@101.5,56.5 v7(102,57) ; D9.AA22@102.5,57.5 v7(102,57)
  Component Side w0.6: C149.1@86.8,50.1 86.3,50.1 86,50.4 85.5,50.9 85.5,52.1 85.9,52.5 C214.1@86.3,52.5 C205.1@87.3,52.5 87.3,53.3 v7(88,54)
  Solder Side w0.18: 96.5,58.5 97.5,58.5
  Solder Side w0.2: 102.5,55.5 103.4,55.5
  Solder Side w0.4: C198.1@87.3,54 v7(88,54) ; v9(96,58) 96.5,58.5 ; 97.5,58.5 v9(98,58) v9(98,57) 98.5,56.5 C209.1@98.5,56.2 ; C197.1@101.2,63.7 101.7,63.7 v9(102,64) ; C199.1@101.454,59.554 101.554,59.554 v9(102,60) v9(103,60) 103.8,60 ; v7(102,56) 102.5,55.5 ; v9(102,71) v13(103,71) ; C200.1@102.8,70.2 103,70.4 v13(103,71) ; C158.1@103,73.8 103.2,73.8 103.8,73.2 103.8,72.8 103.8,71.8 103.5,71.5 103.5,71 ; 103.4,55.5 104,54.9 v2(104,54) 104,53.2 ; C222.1@103.5,53.2 104,53.2 ; C196.1@103.8,59.5 103.8,60 ; C207.1@103.8,60.5 103.8,60 ; C206.1@103.8,63.8 104,63.6 v2(104,63) ; v2(104,71) 103.5,71 ; C201.1@104.5,53.2 104,53.2 ; v2(105,65) 105.6,65 C215.1@105.7,64.9 ; v13(103,71) 103.5,71
  Solder Side w0.5: v1(84,49.2) C157.1@84,50.1 ; C210.1@101.2,55.3 101.2,56.2 101.8,56.2 ; v7(102,56) v7(102,57)
  Solder Side w0.6: C208.1@83,50.1 C157.1@84,50.1 ; C173.1@85.6,50.1 85.6,49.5 v1(85.9,49.2) ; C171.1@102,75.3 102.2,75.3 103,74.5 C158.1@103,73.8
  other v1: 84,48.2 85,48.2 85.9,48.2 85,49.2
D9_1.1V_PCIE: C193.1 C194.1 C195.1 D9.AA6 D9.AD6 L2.2 | length 14.6
  Component Side w0.2: v7(84.9,53) 85.3,53.4 v7(85.8,53.4) ; v7(85,57) v7(86,57)
  Component Side w0.4: v7(85.8,53.4) 86.5,54.1 D9.AD6@86.5,54.5 ; v7(86,57) D9.AA6@86.5,57.5
  Solder Side w0.2: L2.2@80.75,56.55 L2.2@80.8,56.5
  Solder Side w0.5: L2.2@80.75,56.55 L2.2@80.75,56.9 ; L2.2@80.8,56.9 80.8,57.1 81.4,57.7 82.3,57.7 83.7,56.3 84.3,56.3 v7(85,57) v7(86,57) 86.3,57.3 C193.1@86.8,57.3 ; C194.1@84.8,52.2 84.8,52.9 v7(84.9,53) 85.4,53 v7(85.8,53.4) ; C195.1@85.75,56.3 85.75,56.95
FLASH_3.3V: C221.1 C227.2 C239.2 D13.31 D13.41 D13.42 R134.2 R141.1 R142.1 R153.1 XP4.2 | length 70.7
  Component Side w0.5: C239.2@55.6,49.6 C239.2@55.6,49.8 ; C221.1@56.5,47.5 v1(57.5,47.5) ; v1@57.6,49.6 57.9,49.9 R141.1@58.6,49.9
  Component Side w0.8: C239.2@56,49.6 v1(57.5,49.6) ; v1(57.5,47.5) v1(57.5,48.5) v1@57.5,49.5
  Inner Layer 1 w0.2: v1(57.5,64.4) 59,65.9 v1(59,67.8)
  Inner Layer 1 w1: v1(56.7,65.2) v1(57.5,64.4) v1(57.5,63.3) v1(57.5,49.6) v1(57.5,48.5) v1(57.5,47.5)
  Inner Layer 2 w0.2: v1(51.5,64.1) 51.5,65.2
  Inner Layer 2 w1: XP4.2@43.97,67.08 45.85,65.2 51.5,65.2 v1(56.7,65.2) v1(57.5,64.4) v1(57.5,63.3)
  Solder Side w0.15: v1@57.5,49.5 57.5,50.3 59.7,52.5 D13.31@64.75,52.5
  Solder Side w0.2: v1(51.5,64.1) R134.2@52.5,64.1 ; v1(57.5,47.5) 58,47.5 58.5,47 D13.41@58.5,43.75 ; R142.1@57.9,67.8 v1(59,67.8) R153.1@60,67.8
  Solder Side w0.5: C227.2@57.5,40 D13.42@57.5,43.75 v1(57.5,47.5) v1(57.5,48.5) v1@57.5,49.5
FLASH_MISO: D13.20 SA5.8 | length 13.3
  Solder Side w0.15: SA5.8@54.59,72.1 54.59,67.81 55.6,66.8 55.6,62.6 55.5,62.5 D13.20@55.5,59.25
FLASH_MOSI: D13.27 R153.2 SA5.5 | length 14.9
  Solder Side w0.15: SA5.5@62.2,72.09 SA5.5@62.21,72.1 62.21,71.51 61.7,71 61.7,69.6 60.7,68.6 60.7,67.4 60.1,66.8 R153.2@60,66.8 61.9,64.9 61.9,62.7 62.5,62.1 D13.27@62.5,59.25
FLASH_NCE: D13.29 R160.2 SA5.6 | length 22.5
  Inner Layer 1 w0.15: v1(61,54.7) v1(61,69.9)
  Solder Side w0.15: SA5.6@59.67,72.1 59.8,71.97 R160.2@59.8,69.9 v1(61,69.9) ; v1(61,54.7) 61.7,54.7 61.9,54.5 D13.29@64.75,54.5
FLASH_RESET: D13.39 R141.2 XP3.1 | length 33.2
  Component Side w0.15: R141.2@58.6,50.9 59.4,51.7 v1(60,51.7)
  Inner Layer 2 w0.15: XP3.1@46.7,60.57 46.57,60.57 45.5,59.5 45.5,52.8 46.3,52 59.7,52 v1(60,51.7)
  Solder Side w0.15: v1(60,51.7) 60,47.1 60.5,46.6 D13.39@60.5,43.75
FLASH_SCK: D13.26 R142.2 SA5.7 | length 16
  Solder Side w0.15: SA5.7@57.13,72.1 57.13,71.53 56.4,70.8 56.4,69.6 57.2,68.8 57.2,67.4 R142.2@57.7,66.9 ; R142.2@57.9,66.8 58.5,66.2 60,66.2 61.5,64.7 D13.26@61.5,59.25
GEN_XTAL1_IN: R102.1 SA4.6 | length 3.9
  Component Side w0.2: R102.1@120.5,43.2 R102.1@120.6,43.1
  Component Side w0.22: v1(119.4,45.1) 120.5,44 120.5,43.2 R102.1@120.5,43.1
  Solder Side w0.22: v1(119.4,45.1) SA4.6@120.67,45.1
